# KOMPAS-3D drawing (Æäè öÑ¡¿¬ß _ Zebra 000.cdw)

Views: Спереди 1, Спереди, Проекционный вид 2, Проекционный вид 3, Проекционный вид 4, Проекционный вид 5, Проекционный вид 6, Разрез А-А, Вид 8, Вид 9
Referenced files in D:\работа\Чертежи\Компенсатор\ДТК «ФЕНИКС»\: ДТК «ФЕНИКС».m3d
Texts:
  Zebra 000
  ТДК "Феникс"
  Александр
  Лит-Масса-Масштаб
  Материал-Предприятие
  Title Specification
  Body Specification ( left align )
  Body Specificaton ( centered )
  Поз.
  Кол.
  Приме-
  чание
  Таблица спецификации
  Сталь 20  ГОСТ 1050-88
  Чередниченко А.В.
  Zebra 000-
Dimensions and other numbers on the sheet: 2; 17; 65; 20; 12; 22; 4; 8; 14Х1L; 7; 18; 11; 30; 19; 1; 0; 1:1; 0,13; 18.06.2015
